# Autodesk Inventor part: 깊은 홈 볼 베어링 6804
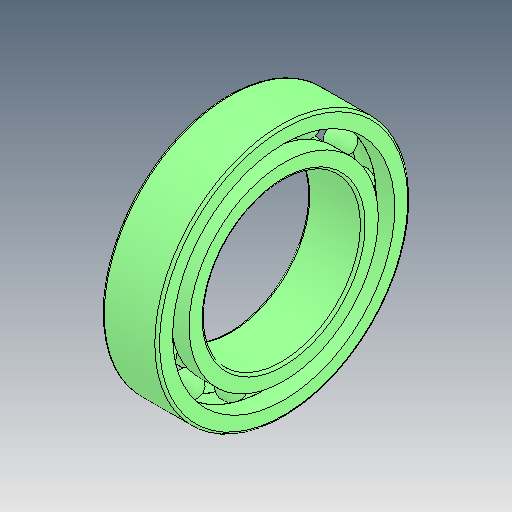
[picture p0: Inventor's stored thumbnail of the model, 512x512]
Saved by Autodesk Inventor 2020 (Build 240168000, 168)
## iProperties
Created: 2025-01
Part Number: 깊은 홈 볼 베어링 6804
Material: 강철, 연강
Description: 깊은 그루부 볼 베어링
Document SubType Name: Modeling
Designer: 1강의실14
Density: 7.85 g/cm^3
Appearance: 기본값
Author: jhkim
Sending System: Autodesk Inventor 2025
Preprocessor: ST-DEVELOPER v20
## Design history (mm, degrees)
feature "Solid1"
feature "Solid1:1"
feature "Solid1:2"
feature "Solid1:3"
feature "Solid1:4"
feature "Solid1:5"
feature "Solid1:6"
feature "Solid1:7"
feature "Solid1:8"
feature "Solid1:9"
feature "Solid1:10"
feature "Solid1:11"
feature "Solid1:12"
feature "Solid1:13"
feature "Solid1:14"
node "솔리드1"
node "솔리드2"
node "솔리드3"
node "솔리드4"
node "솔리드5"
node "솔리드6"
node "솔리드7"
node "솔리드8"
node "솔리드9"
node "솔리드10"
node "솔리드11"
node "솔리드12"
node "솔리드13"
node "솔리드14"
node "솔리드15"
